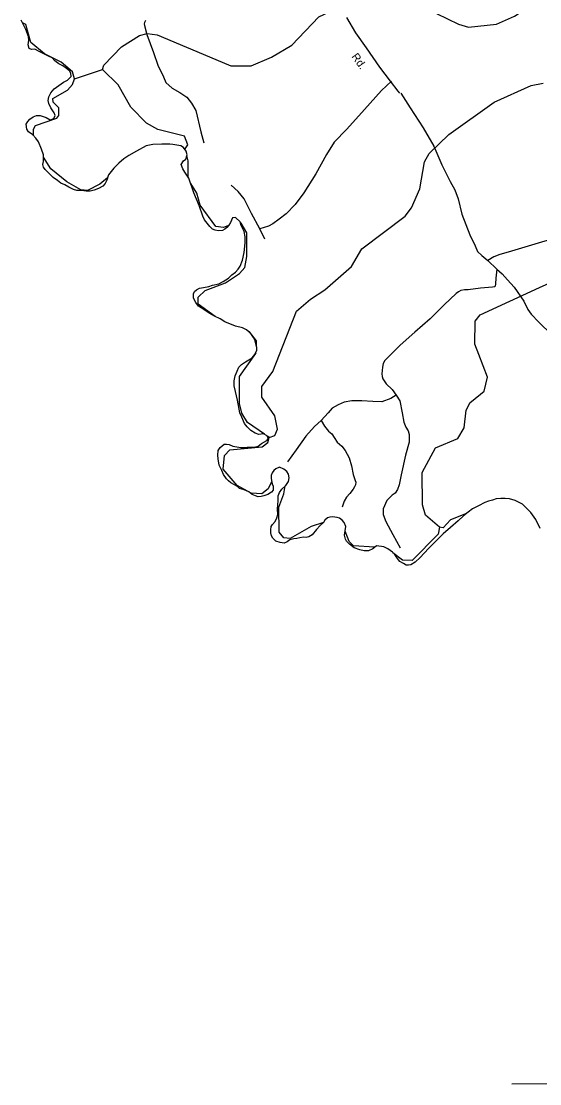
# Model space of a CAD drawing. Extents: x 2093524 to 2270757, y 289120 to 570408.
# Drawn here: x 2206650 to 2212810, y 303848 to 316455 of the extents above; entities that cross this region are included whole.
import ezdxf

# ---------------------------------------------------------------- set-up
doc = ezdxf.new("R2010")
doc.units = 0
for name, color, linetype in [('Exist Boundary Political CountyLine', 7, 'Continuous'), ('Exist Hydrographic Misc Water Feature', 7, 'Continuous'), ('Exist Road Non-System Type 51', 7, 'Continuous'), ('Exist Road Secondary Type 51 Attributed', 7, 'Continuous'), ('Exist Road Secondary Type 51 Label', 7, 'Continuous'), ('Map Preparation Longitude Latitude Lines', 7, 'Continuous')]:
    doc.layers.add(name, color=color, linetype=linetype)

msp = doc.modelspace()

# ---------------------------------------------------------------- linework, layer by layer
at = {"layer": 'Exist Boundary Political CountyLine'}
for points in [[(2208643, 314595), (2208595, 314665), (2208570, 314703), (2208550, 314755), (2208578, 314800), (2208604, 314819), (2208620, 314871), (2208611, 314914), (2208578, 314958), (2208546, 314975), (2208499, 314983), (2208452, 314992), (2208414, 314995), (2208369, 314998), (2208322, 314995), (2208215, 314991), (2208136, 314975), (2208018, 314915), (2207928, 314863), (2207870, 314823), (2207809, 314770), (2207750, 314713), (2207687, 314632), (2207668, 314569), (2207648, 314529), (2207620, 314500), (2207567, 314469), (2207515, 314450), (2207468, 314440), (2207423, 314440), (2207364, 314445), (2207312, 314448), (2207272, 314459), (2207217, 314485), (2207168, 314515), (2207119, 314535), (2207080, 314567), (2207030, 314602), (2207000, 314633), (2206963, 314668), (2206933, 314696), (2206914, 314722), (2206907, 314756), (2206914, 314792), (2206914, 314872), (2206890, 314938), (2206854, 315024), (2206824, 315066), (2206788, 315107), (2206736, 315145), (2206719, 315175), (2206710, 315233), (2206728, 315265), (2206753, 315295), (2206792, 315323), (2206830, 315336), (2206877, 315336), (2206946, 315312), (2206995, 315287), (2207036, 315302), (2207052, 315336), (2207042, 315370), (2207004, 315428), (2206978, 315481), (2206971, 315516), (2206980, 315560), (2207004, 315607), (2207042, 315652), (2207151, 315734), (2207199, 315758), (2207242, 315801), (2207240, 315840), (2207225, 315865), (2207190, 315895), (2207146, 315927), (2207096, 315951), (2207049, 315985), (2207017, 316021), (2206976, 316040), (2206905, 316076), (2206864, 316095), (2206813, 316125), (2206772, 316121), (2206745, 316132), (2206734, 316174), (2206740, 316230), (2206738, 316273), (2206704, 316358), (2206650, 316470)], [(2209112, 311001), (2209090, 311027), (2209052, 311078), (2209032, 311126), (2209000, 311188), (2208988, 311261), (2208985, 311307), (2208991, 311362), (2209012, 311399), (2209060, 311435), (2209090, 311438), (2209122, 311431), (2209164, 311415), (2209210, 311406), (2209260, 311397), (2209297, 311396), (2209335, 311400), (2209375, 311402), (2209425, 311403), (2209466, 311415), (2209504, 311444), (2209569, 311481), (2209582, 311509), (2209573, 311536), (2209529, 311558), (2209474, 311551), (2209431, 311567), (2209379, 311600), (2209334, 311643), (2209304, 311684), (2209271, 311759), (2209246, 311810), (2209218, 311960), (2209195, 312060), (2209180, 312130), (2209180, 312188), (2209190, 312249), (2209214, 312304), (2209236, 312352), (2209268, 312381), (2209316, 312413), (2209393, 312461), (2209425, 312499), (2209451, 312551), (2209450, 312582), (2209437, 312629), (2209431, 312663), (2209410, 312704), (2209386, 312739), (2209360, 312764), (2209327, 312794), (2209280, 312816), (2209196, 312838), (2209068, 312890), (2209014, 312923), (2208947, 312956), (2208884, 312991), (2208832, 313025), (2208757, 313075), (2208725, 313117), (2208696, 313169), (2208698, 313221), (2208708, 313248), (2208731, 313270), (2208770, 313289), (2208817, 313297), (2208878, 313306), (2208922, 313323), (2208997, 313338), (2209048, 313369), (2209114, 313407), (2209153, 313447), (2209196, 313479), (2209228, 313513), (2209252, 313551), (2209277, 313620), (2209297, 313711), (2209309, 313826), (2209310, 313896), (2209298, 313962), (2209265, 314032), (2209250, 314077), (2209194, 314127), (2209161, 314121), (2209147, 314096), (2209135, 314069), (2209115, 314034), (2209094, 314008), (2209070, 313989), (2209042, 313974), (2208990, 313970), (2208953, 313977), (2208922, 313989), (2208890, 314018), (2208858, 314060), (2208829, 314099), (2208806, 314142), (2208763, 314267), (2208702, 314421), (2208643, 314595)], [(2212158, 310743), (2212081, 310705), (2212012, 310668), (2211959, 310631), (2211904, 310585), (2211840, 310527), (2211750, 310450), (2211661, 310373), (2211623, 310334), (2211489, 310199), (2211391, 310091), (2211328, 310037), (2211278, 310007), (2211250, 310002), (2211223, 310002), (2211191, 310019), (2211148, 310044), (2211119, 310079), (2211087, 310128), (2211061, 310155), (2211004, 310195), (2210957, 310218), (2210870, 310230), (2210826, 310196), (2210777, 310172), (2210726, 310172), (2210671, 310183), (2210607, 310206), (2210549, 310250), (2210514, 310287), (2210503, 310311), (2210491, 310358), (2210508, 310461), (2210486, 310507), (2210464, 310536), (2210433, 310557), (2210402, 310566), (2210375, 310571), (2210344, 310574), (2210315, 310571), (2210288, 310562), (2210256, 310534), (2210240, 310508), (2210202, 310472), (2210156, 310423), (2210107, 310361), (2210068, 310339), (2210036, 310330), (2210003, 310332), (2209960, 310326), (2209925, 310316), (2209888, 310313), (2209841, 310301), (2209810, 310278), (2209775, 310261), (2209727, 310271), (2209674, 310287), (2209638, 310322), (2209624, 310348), (2209616, 310383), (2209614, 310420), (2209618, 310459), (2209634, 310484), (2209665, 310521), (2209685, 310564), (2209699, 310604), (2209694, 310668), (2209703, 310766), (2209702, 310825), (2209718, 310865), (2209748, 310902), (2209792, 310948), (2209826, 310994), (2209833, 311039), (2209827, 311079), (2209806, 311113), (2209769, 311140), (2209720, 311163), (2209673, 311146), (2209650, 311125), (2209630, 311096), (2209621, 311065), (2209619, 311029), (2209632, 310968), (2209644, 310940), (2209642, 310893), (2209625, 310868), (2209578, 310839), (2209532, 310824), (2209500, 310815), (2209463, 310813), (2209434, 310822), (2209393, 310841), (2209356, 310870), (2209297, 310896), (2209243, 310911), (2209219, 310935), (2209182, 310954), (2209142, 310977), (2209112, 311001)], [(2212816, 310437), (2212764, 310543), (2212704, 310625), (2212643, 310686), (2212604, 310726), (2212567, 310744), (2212516, 310767), (2212449, 310789), (2212399, 310793), (2212346, 310792), (2212292, 310789), (2212248, 310773), (2212200, 310760), (2212158, 310743)]]:
    msp.add_lwpolyline(points, dxfattribs=at)
at = {"layer": 'Exist Hydrographic Misc Water Feature'}
for p, q in [((2207285, 315773), (2207617, 315881)), ((2207617, 315881), (2207633, 315933))]:
    msp.add_line(p, q, dxfattribs=at)
for points in [[(2208961, 316002), (2209142, 315927), (2209382, 315928), (2209624, 316029), (2209865, 316171), (2210186, 316509), (2210370, 316594), (2210859, 316713), (2211102, 316705), (2211452, 316609), (2211845, 316421), (2211962, 316386), (2212295, 316422), (2212511, 316516), (2212792, 316701)], [(2207285, 315773), (2207259, 315855), (2207124, 315970), (2206925, 316069), (2206765, 316203), (2206706, 316417), (2206667, 316436)], [(2207633, 315933), (2207840, 316152), (2208056, 316286), (2208146, 316310), (2208264, 316295), (2208961, 316002)], [(2208599, 314940), (2208631, 314989), (2208589, 315091), (2208272, 315170), (2208138, 315244), (2207953, 315435), (2207802, 315700), (2207617, 315881)], [(2206797, 315096), (2206797, 315176), (2206822, 315218), (2207072, 315305), (2207096, 315337), (2207096, 315429), (2207028, 315496), (2207027, 315539), (2207202, 315637), (2207260, 315705), (2207285, 315773)], [(2209597, 311515), (2209663, 311540), (2209696, 311615), (2209661, 311773), (2209510, 311996), (2209509, 312121), (2209640, 312299), (2209920, 313015), (2210085, 313159), (2210258, 313267), (2210574, 313546), (2210696, 313754), (2211211, 314141), (2211285, 314241), (2211384, 314468), (2211440, 314786), (2211498, 314886), (2211728, 315111), (2212268, 315497), (2212708, 315692), (2212849, 315719)], [(2207676, 314597), (2207585, 314524), (2207436, 314448), (2207360, 314456), (2207193, 314548), (2207001, 314703), (2206914, 314842)], [(2208599, 314940), (2208595, 314941)], [(2208600, 314936), (2208599, 314940)], [(2208633, 314609), (2208633, 314798), (2208617, 314863)], [(2209113, 314031), (2209055, 314009), (2208963, 314018), (2208778, 314274), (2208735, 314416), (2208664, 314531)], [(2208955, 312952), (2208753, 313100), (2208752, 313182), (2208835, 313259), (2209076, 313353), (2209242, 313461), (2209307, 313535), (2209331, 313663), (2209330, 313945), (2209263, 314061), (2209255, 314061)], [(2211620, 310452), (2211451, 310593), (2211418, 310718), (2211415, 311102), (2211572, 311394), (2211837, 311504), (2211912, 311631), (2211935, 311840), (2211984, 311931), (2212001, 311945), (2212150, 312065), (2212190, 312232), (2212086, 312499), (2212037, 312622), (2212044, 312897), (2212101, 312972), (2212808, 313294), (2212991, 313377)], [(2209444, 312604), (2209446, 312663), (2209363, 312770), (2209348, 312775)], [(2209539, 311555), (2209337, 311694), (2209269, 311804), (2209243, 311919), (2209242, 312238), (2209439, 312512), (2209440, 312521)], [(2209624, 310988), (2209583, 310906), (2209510, 310848), (2209383, 310856), (2209217, 310946), (2209048, 311142), (2209064, 311303), (2209130, 311370), (2209514, 311406), (2209580, 311457), (2209597, 311515)], [(2209597, 311515), (2209579, 311527)], [(2210240, 310507), (2210094, 310459), (2209845, 310317), (2209770, 310325), (2209713, 310391), (2209710, 310690), (2209768, 310849), (2209786, 310942)], [(2211939, 310615), (2211751, 310538), (2211661, 310445), (2211620, 310452)], [(2210845, 310216), (2210597, 310230), (2210546, 310280), (2210498, 310403)], [(2211620, 310452), (2211604, 310370), (2211296, 310058), (2211181, 310061), (2211066, 310149)]]:
    msp.add_lwpolyline(points, dxfattribs=at)
at = {"layer": 'Exist Road Non-System Type 51'}
for p, q in [((2209543, 313868), (2209483, 313993)), ((2212192, 313618), (2212298, 313515))]:
    msp.add_line(p, q, dxfattribs=at)
for points in [[(2208127, 316463), (2208116, 316442), (2208112, 316423), (2208114, 316403), (2208142, 316297), (2208220, 316086), (2208274, 315934), (2208339, 315795), (2208370, 315727), (2208443, 315663), (2208534, 315608), (2208617, 315556), (2208674, 315485), (2208723, 315395), (2208782, 315145), (2208820, 315013)], [(2211048, 315743), (2210930, 315633), (2210728, 315410), (2210520, 315176), (2210367, 315020), (2210276, 314876), (2210149, 314646), (2210009, 314420), (2209904, 314280), (2209796, 314171), (2209715, 314105), (2209640, 314052), (2209586, 314025), (2209483, 313993)], [(2211159, 315601), (2211272, 315429), (2211426, 315192), (2211551, 314972), (2211645, 314752), (2211746, 314553), (2211800, 314454), (2211840, 314349), (2211883, 314168), (2211979, 313922), (2212043, 313791), (2212072, 313724), (2212123, 313676), (2212192, 313618)], [(2209483, 313993), (2209386, 314174), (2209297, 314350), (2209229, 314437), (2209146, 314511)], [(2213194, 313932), (2213081, 313906), (2212872, 313845), (2212633, 313773), (2212434, 313714), (2212335, 313688), (2212264, 313659), (2212192, 313618)], [(2212298, 313515), (2212288, 313405), (2212285, 313341), (2212281, 313313), (2212271, 313304), (2212247, 313301), (2212106, 313288), (2211958, 313270), (2211916, 313267), (2211872, 313260), (2211843, 313246), (2211815, 313224), (2211673, 313089), (2211510, 312924), (2211325, 312765), (2211152, 312613), (2210969, 312430), (2210951, 312393), (2210940, 312351), (2210934, 312273), (2210937, 312240), (2210947, 312211), (2210986, 312154), (2211055, 312085), (2211104, 312020)], [(2212298, 313515), (2212363, 313459), (2212428, 313388), (2212505, 313299), (2212620, 313135), (2212668, 313034), (2212707, 312979), (2212800, 312884), (2212853, 312829), (2212892, 312792), (2212940, 312771), (2213116, 312770), (2213464, 312784), (2213588, 312788), (2213724, 312792)], [(2211104, 312020), (2211039, 311979), (2210933, 311941), (2210829, 311944), (2210697, 311953), (2210579, 311951), (2210487, 311934), (2210414, 311904), (2210345, 311865), (2210298, 311808), (2210215, 311717)], [(2211104, 312020), (2211149, 311953), (2211176, 311809), (2211197, 311698), (2211218, 311638), (2211245, 311595), (2211260, 311551), (2211259, 311461), (2211214, 311305), (2211164, 311074), (2211138, 310953), (2211121, 310897), (2211092, 310857), (2211058, 310832), (2210993, 310769), (2210951, 310670), (2210950, 310602), (2210981, 310521), (2211064, 310364), (2211151, 310206)], [(2210215, 311717), (2210135, 311646), (2210033, 311530), (2209918, 311370), (2209812, 311227)], [(2210215, 311717), (2210253, 311650), (2210299, 311593), (2210342, 311559), (2210369, 311516), (2210402, 311460), (2210458, 311414), (2210499, 311362), (2210547, 311273), (2210572, 311178), (2210594, 311076), (2210619, 311004), (2210624, 310985), (2210620, 310956), (2210611, 310929), (2210595, 310904), (2210554, 310850), (2210513, 310809), (2210488, 310759), (2210461, 310688)]]:
    msp.add_lwpolyline(points, dxfattribs=at)
at = {"layer": 'Exist Road Secondary Type 51 Attributed'}
msp.add_lwpolyline([(2210513, 316501), (2210620, 316317), (2210747, 316140), (2210908, 315911), (2211031, 315743), (2211125, 315627), (2211142, 315601)], dxfattribs=at)
at = {"layer": 'Map Preparation Longitude Latitude Lines'}
msp.add_line((2212479, 303848), (2221972, 303915), dxfattribs=at)

# ---------------------------------------------------------------- texts
at = {"layer": 'Exist Road Secondary Type 51 Label'}
msp.add_text('Rd.', height=95, rotation=305.5304, dxfattribs=at).set_placement((2210568, 316035))

doc.saveas('drawing.dxf')
